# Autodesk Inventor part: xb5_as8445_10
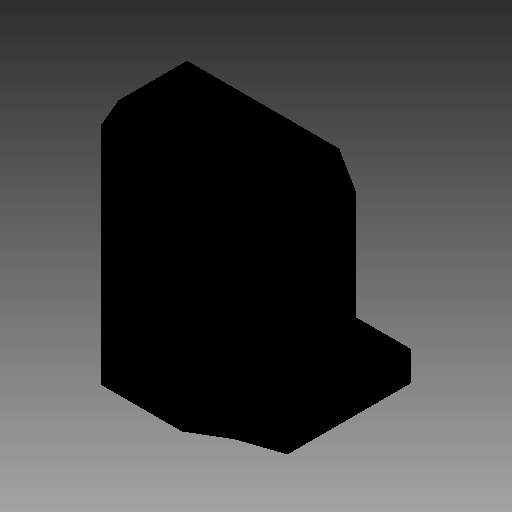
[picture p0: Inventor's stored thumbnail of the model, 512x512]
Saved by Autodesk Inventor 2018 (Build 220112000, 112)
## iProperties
Company: TraceParts S.A.
Created: 2018-04
Part Number: xb5_as8445_10
Checked By: TraceParts S.A.
Material: Generic
Catalog Web Link: www.traceparts.com
Document SubType Name: Modeling
Designer: TraceParts
Density: 1 g/cm^3
Appearance: Default
Author: TraceParts
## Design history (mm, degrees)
feature "xb5_as8445_10.ipt"
body "Solid1"
